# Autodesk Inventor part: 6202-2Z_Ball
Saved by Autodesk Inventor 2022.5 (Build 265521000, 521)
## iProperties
Created: 2024-12
Part Number: 6202-2Z_Ball
Material: Generic
Document SubType Name: Modeling
Designer: AdminForWorker
Density: 1 g/cm^3
Appearance: Default
Title: 6202-2Z_Ball
Author: AdminForWorker
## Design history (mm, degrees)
feature "Body1"
body "Solid1"
